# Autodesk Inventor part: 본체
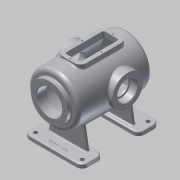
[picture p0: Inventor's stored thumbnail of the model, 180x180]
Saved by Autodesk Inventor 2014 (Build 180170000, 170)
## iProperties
Created: 2016-02
Part Number: 본체
Material: 알루미늄 6061
Document SubType Name: Modeling
Designer: mduedu
Density: 2.71 g/cm^3
Appearance: 알루미늄 - 평지
Mass: 3305.58 g
Surface Area: 2487 cm^2
Volume: 1219.77 cm^3
Author: mduedu
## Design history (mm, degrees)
sketch "스케치2"
  geometry: L1 (0, 100)-(0, -100); L2 (65, -87.083)-(65, 100); L3 (65, 100)-(0, 100); A1 r 170 centre (0, 70) between (0, -100) and (65, -87.083); 2 further points
  constraints: 6 end point, 2 point on circle, 1 centre point, 1 coincident, 1 horizontal, 1 midpoint, 1 parallel, 1 point on line, 1 vertical
  dimensions: "d3" = 200 distance of L1.start L1.end; "d5" = 130 diameter of L2 L1; "d6" = 170 radius of A1
revolve "회전1" sketch "스케치2" stored, may be unused: angle "d7" = 90 deg
sketch "스케치3"
  geometry: C1 r 47.5 at (0, 0); 1 further point
  constraints: 1 centre point, 1 coincident
  dimensions: "d8" = 95 diameter of C1
extrude "돌출2" join sketch "스케치3" distance "d10" = 10; taper "d11" = 0 deg
sketch "스케치5"
  geometry: L1 (47.5, 110)-(47.5, 100) reference; L2 (47.5, 100)-(65, 100) reference; L3 (65, 100)-(65, -87.083) reference; L4 (-65, -87.083)-(-65, 100) reference; L5 (-65, 100)-(-47.5, 100) reference; L6 (-47.5, 100)-(-47.5, 110) reference; L7 (-47.5, 110)-(47.5, 110) reference; L8 (55, 85)-(55, -80.25); L9 (0, 85)-(55, 85); L10 (0, 85)-(0, -90); A1 r 170 centre (0, 70) between (-65, -87.083) and (0, -100) reference; A2 r 170 centre (0, 70) between (0, -100) and (65, -87.083) reference; A3 r 160 centre (0, 70) between (0, -90) and (55, -80.25); 1 further point
  constraints: 6 end point, 2 point on circle, 1 centre point, 1 parallel, 1 perpendicular, 1 point on line, 1 vertical
  dimensions: "d13" = 10 distance between parallel lines of L3 L8; "d14" = 10 radial gap between concentric circles of A3 A1; "d15" = 15 distance between parallel lines of L9 L2
revolve "회전2" sketch "스케치5" stored, may be unused: angle "d16" = 90 deg
hole "구멍1" diameter "d19" = 65; stored, may be unused: countersink angle "d23" = 90 deg, drill point angle "d25" = 118 deg; dims "d17" = 10, "d18" = 10, "d20" = 6, "d21" = 4, "d22" = 2, "d24" = 8
node "작업 평면1"
sketch "스케치6"
  geometry: L1 (47.5, 110)-(-47.5, 110) reference; C1 r 40 at (0, -17); 1 further point
  constraints: 1 centre point, 1 vertical alignment
  dimensions: "d27" = 80 diameter of C1; "d29" = 127 distance from line of C1.centre L1
extrude "돌출3" join sketch "스케치6" stored distance "d30" = 10; taper "d31" = 0 deg
hole "구멍2" diameter "d34" = 42; stored, may be unused: countersink angle "d38" = 90 deg, drill point angle "d40" = 118 deg; dims "d32" = 10, "d33" = 10, "d35" = 6, "d36" = 52, "d37" = 18, "d39" = 8
sketch "스케치7" dims "d41" = 65
  geometry: C1 r 40 at (0, 0) reference; 3 further points
  constraints: 2 vertical alignment, 1 coincident, 2 other
hole "구멍3" sketch "스케치7" at (0, 32.5) diameter "d43" = 3.242; stored, may be unused: countersink angle "d47" = 90 deg, drill point angle "d49" = 118 deg; dims "d44" = 11, "d45" = 13, "d46" = 18, "d48" = 13
sketch "스케치8" dims "d53" = 80
  geometry: 3 further points
  constraints: 2 vertical alignment, 1 coincident, 2 other
hole "구멍4" sketch "스케치8" at (0, 40) diameter "d56" = 3.242; stored, may be unused: countersink angle "d60" = 90 deg, drill point angle "d62" = 118 deg; dims "d57" = 11, "d58" = 13, "d59" = 18, "d61" = 13
fillet "모깎기1" dims "d66" = 10
fillet "모깎기2" dims "d67" = 3
fillet "모깎기3" dims "d68" = 0.3
chamfer "모따기1" distance "d69" = 1; stored, may be unused: second distance "d70" = 2, angle "d71" = 45 deg
node "작업 평면2"
sketch "스케치9"
  geometry: L1 (75, 100)-(-75, 100); L2 (-75, 100)-(-75, -100); L3 (-75, -100)-(75, -100); L4 (75, -100)-(75, 100); 1 further point
  constraints: 8 end point, 2 parallel, 1 horizontal, 1 perpendicular
  dimensions: "d73" = 200 distance of L3.end L1.start; "d75" = 150 distance of L2.end L3.end; "d76" = 100 distance from line of L1 point (0, 0); "d77" = 75 distance from line of L4 point (0, 0)
extrude "돌출4" join sketch "스케치9" distance "d78" = 10; taper "d79" = 0 deg
sketch "스케치10"
  geometry: L1 (-75, -100)-(75, -100) reference; L2 (75, 100)-(-75, 100) reference; L3 (0, -100)-(0, 100); L4 (-75, 100)-(-75, -100) reference; L5 (75, -100)-(75, 100) reference; L6 (-75, 0)-(75, 0); L7 (-50, -63)-(50, -63); L8 (50, -63)-(50, -55); L9 (50, -55)-(-50, -55); L10 (-50, -55)-(-50, -63); L11 (-50, 63)-(50, 63); L12 (50, 63)-(50, 55); L13 (50, 55)-(-50, 55); L14 (-50, 55)-(-50, 63); 1 further point
  constraints: 20 end point, 4 midpoint, 4 symmetric about line, 2 parallel, 1 horizontal, 1 perpendicular, 1 other
  dimensions: "d80" = 8 distance of L9.end L7.start; "d82" = 100 distance of L7.start L7.end; "d83" = 55 distance between parallel lines of L9 L6
extrude "돌출5" join sketch "스케치10" stored distance "d84" = 10; taper "d85" = 0 deg
feature "면 기울기1" dims angle "d86" = 10 deg
sketch "스케치11"
  geometry: L1 (-110, 55)-(-51.482, 55) reference; L2 (-110, -55)-(-51.482, -55) reference; L3 (-95, 55)-(-95, -55); L4 (-65, 90)-(-65, -80.25) reference; 1 further point
  constraints: 2 end point, 2 point on line, 1 perpendicular
  dimensions: "d87" = 30 distance between parallel lines of L3 L4
feature "리브1" sketch "스케치11" dims "d88" = 1, "d89" = 8, "d90" = 0, "d91" = 0, "d92" = 1, "d93" = 1
sketch "스케치12"
  geometry: L1 (-110, 55)-(-51.482, 55) reference; L2 (-110, -55)-(-51.482, -55) reference; L3 (-110, 100)-(-110, -100) reference; L4 (-120, 152)-(-120, -142) reference; L5 (-110, 45)-(-120, 45); L6 (-120, 45)-(-120, -45); L7 (-120, -45)-(-110, -45); L8 (-110, -45)-(-110, 45); 1 further point
  constraints: 8 end point, 2 parallel, 2 point on line, 1 horizontal, 1 perpendicular
  dimensions: "d94" = 10 distance between parallel lines of L7 L2; "d95" = 10 distance between parallel lines of L1 L5
extrude "돌출6" cut sketch "스케치12" stored distance "d96" = 10; taper "d97" = 0 deg
fillet "모깎기4" dims "d98" = 15
sketch "스케치13"
  geometry: C1 r 5 at (-60, -85); C2 r 5 at (60, -85); C3 r 5 at (60, 85); C4 r 5 at (-60, 85); A1 r 15 centre (-60, -85) between (-75, -85) and (-60, -100) reference; A2 r 15 centre (60, -85) between (60, -100) and (75, -85) reference; A3 r 15 centre (60, 85) between (75, 85) and (60, 100) reference; A4 r 15 centre (-60, 85) between (-60, 100) and (-75, 85) reference; 1 further point
  constraints: 4 centre point, 4 coincident, 3 equal radius
  dimensions: "d99" = 10 diameter of C1
extrude "돌출7" cut sketch "스케치13" stored distance "d101" = 10; taper "d102" = 0 deg
fillet "모깎기5" dims "d103" = 3, "d104" = 3
fillet "모깎기6" dims "d105" = 3
sketch "스케치14"
  geometry: L1 (-60, -100)-(60, -100) reference; 2 further points
  constraints: 1 vertical alignment, 1 other
  dimensions: "d106" = 15 distance from line of point (0, -85) L1
feature "엠보싱1" sketch "스케치14" dims "d3" = 200, "d5" = 130, "d6" = 170, "d14" = 10, "d107" = 0.5, "d108" = 0
node "작업 평면3"
sketch "스케치15"
  geometry: L1 (-30, 60)-(30, 60); L2 (30, 60)-(30, -60); L3 (30, -60)-(-30, -60); L4 (-30, -60)-(-30, 60); 2 further points
  constraints: 8 end point, 2 parallel, 1 horizontal, 1 midpoint, 1 perpendicular, 1 vertical alignment
  dimensions: "d110" = 60 distance of L2.end L3.end; "d112" = 60 distance from line of L3 point (0, 0); "d113" = 120 distance of L1.end L2.end
extrude "돌출8" join sketch "스케치15" stored distance "d114" = 10; taper "d115" = 0 deg
fillet "모깎기7" dims "d116" = 15
sketch "스케치16"
  geometry: L1 (-30, -45)-(-30, 45) reference; L2 (-15, 60)-(15, 60) reference; L3 (30, 45)-(30, -45) reference; L4 (15, -60)-(-15, -60) reference; L5 (15, 50)-(-15, 50); L6 (-20, 45)-(-20, -45); L7 (-15, -50)-(15, -50); L8 (20, -45)-(20, 45); A1 r 15 centre (-15, -45) between (-30, -45) and (-15, -60) reference; A2 r 15 centre (-15, 45) between (-15, 60) and (-30, 45) reference; A3 r 15 centre (15, 45) between (30, 45) and (15, 60) reference; A4 r 15 centre (15, -45) between (15, -60) and (30, -45) reference; A5 r 5 centre (-15, 45) between (-15, 50) and (-20, 45); A6 r 5 centre (-15, -45) between (-20, -45) and (-15, -50); A7 r 5 centre (15, -45) between (15, -50) and (20, -45); A8 r 5 centre (15, 45) between (20, 45) and (15, 50); 1 further point
  constraints: 8 end point, 8 point on circle, 4 centre point, 7 other
  dimensions: "d117" = 10 distance between parallel lines of L6 L1
extrude "돌출9" cut sketch "스케치16" stored distance "d118" = 10; taper "d119" = 0 deg
fillet "모깎기8" dims "d120" = 3
sketch "스케치17"
  geometry: L1 (-30, -45)-(-30, 45) reference; L2 (-15, 60)-(15, 60) reference; L3 (30, 45)-(30, -45) reference; L4 (15, -60)-(-15, -60) reference; L5 (20, -45)-(20, 45) reference; L6 (15, 50)-(-15, 50) reference; L7 (-20, 45)-(-20, -45) reference; L8 (-15, -50)-(15, -50) reference; L9 (15, 55)-(-15, 55); L10 (-25, 45)-(-25, -45); L11 (-15, -55)-(15, -55); L12 (25, -45)-(25, 45); A1 r 15 centre (-15, 45) between (-15, 60) and (-30, 45) reference; A2 r 15 centre (15, 45) between (30, 45) and (15, 60) reference; A3 r 15 centre (15, -45) between (15, -60) and (30, -45) reference; A4 r 15 centre (-15, -45) between (-30, -45) and (-15, -60) reference; A5 r 5 centre (15, -45) between (15, -50) and (20, -45) reference; A6 r 5 centre (15, 45) between (20, 45) and (15, 50) reference; A7 r 5 centre (-15, 45) between (-15, 50) and (-20, 45) reference; A8 r 5 centre (-15, -45) between (-20, -45) and (-15, -50) reference; A9 r 10 centre (-15, 45) between (-15, 55) and (-25, 45); A10 r 10 centre (-15, -45) between (-25, -45) and (-15, -55); A11 r 10 centre (15, -45) between (15, -55) and (25, -45); A12 r 10 centre (15, 45) between (25, 45) and (15, 55); 5 further points
  constraints: 8 end point, 8 point on circle, 4 centre point, 4 midpoint, 7 other
  dimensions: "d121" = 5 distance between parallel lines of L10 L1
hole "구멍5" sketch "스케치17" at (0, 55), (25, 0), (0, -55), (-25, 0) diameter "d122" = 3.242; stored, may be unused: countersink angle "d126" = 90 deg, drill point angle "d128" = 118 deg; dims "d123" = 9, "d124" = 13, "d125" = 18, "d127" = 11
fillet "모깎기9" dims "d129" = 3
node "솔리드2"
pattern_circular "원형 패턴1" dims angle "d51" = 360 deg
mirror "대칭1"
pattern_circular "원형 패턴2" dims angle "d64" = 360 deg
node "절단 모서리 투영1"
node "절단 모서리 투영2"
node "절단 모서리 투영3"
other parameters: "d26" = 75
